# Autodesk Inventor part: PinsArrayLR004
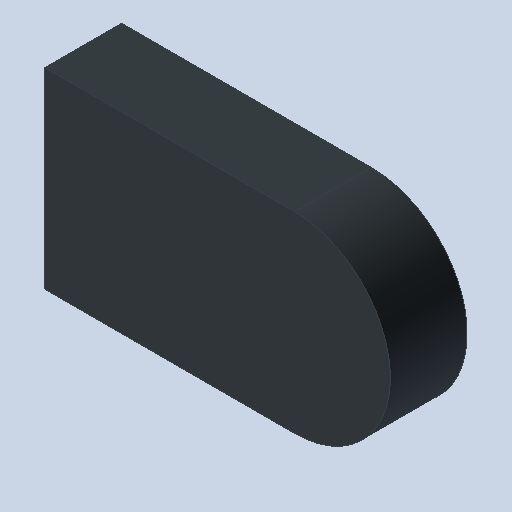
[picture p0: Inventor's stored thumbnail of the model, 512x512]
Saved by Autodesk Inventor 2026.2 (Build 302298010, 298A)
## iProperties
Created: 2026-10
Part Number: PinsArrayLR004
Material: Générique
Document SubType Name: Modeling
Designer: mel
Density: 1 g/cm^3
Appearance: Par défaut
Author: mel
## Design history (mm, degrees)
feature "Base1"
node "Solide1"
